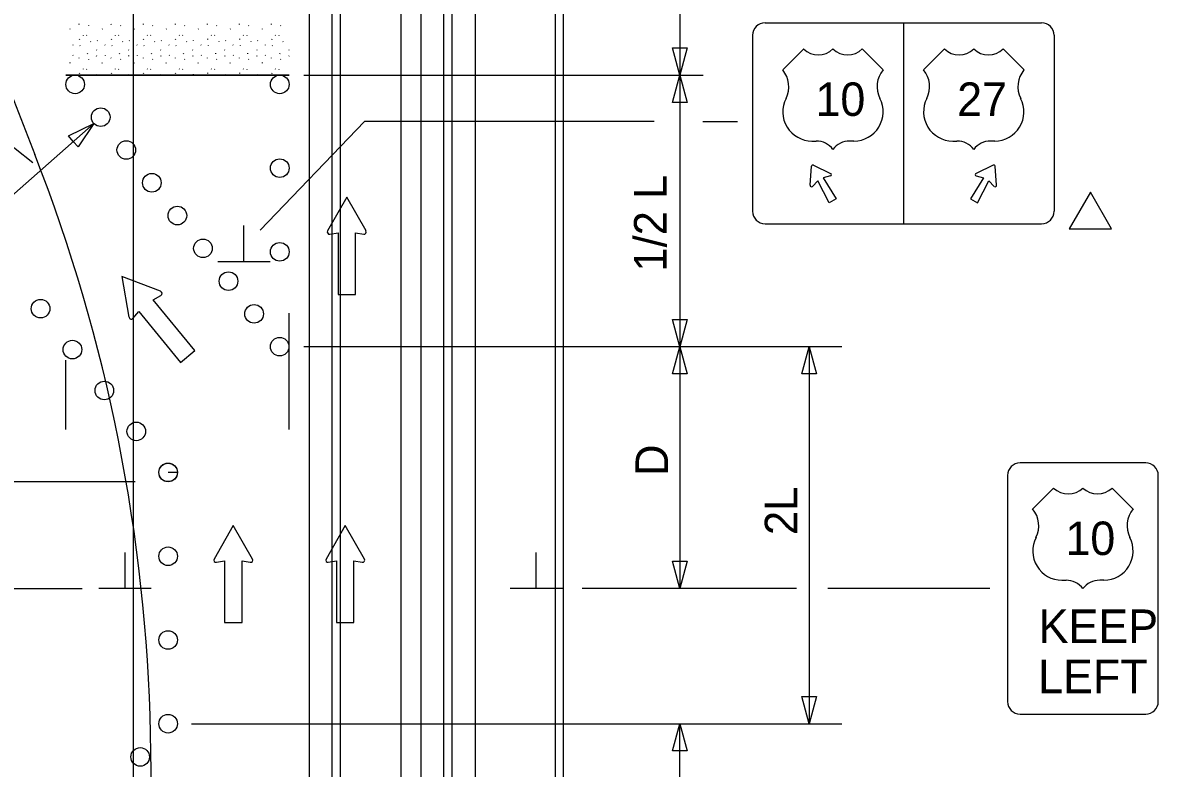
# Model space of a CAD drawing. Extents: x 16715 to 19504, y 7040 to 8495.
# Drawn here: x 16934 to 17178.1, y 7602.5 to 7762.8 of the extents above; entities that cross this region are included whole.
import ezdxf

# ---------------------------------------------------------------- set-up
doc = ezdxf.new("R2010")
doc.units = 0
for name, color, linetype in [('ALI_LEGAL_EX', 7, 'Continuous'), ('MT_SCRATCH_LEVEL_A', 7, 'Continuous'), ('MT_SCRATCH_LEVEL_E', 7, 'Continuous'), ('PAVT_EDGE_EX', 7, 'Continuous'), ('TRAFFIC_SIGNS_PR', 7, 'Continuous'), ('TYPICAL_EX', 7, 'Continuous'), ('TYPICAL_TEXT_DIMEN_PR', 7, 'Continuous')]:
    doc.layers.add(name, color=color, linetype=linetype)

msp = doc.modelspace()

# ---------------------------------------------------------------- linework, layer by layer
at = {"layer": 'ALI_LEGAL_EX'}
for p, q in [((16714.57, 8302.79), (16936.6, 7734.43)), ((16995.53, 8241.3), (16995.53, 7423.16)), ((17019.53, 8241.3), (17019.53, 7423.16)), ((17000.51, 7366.28), (17000.51, 7976.48)), ((17024.51, 7366.28), (17024.51, 7976.48)), ((17048.51, 7366.28), (17048.51, 7976.48)), ((17002.26, 7363.06), (17002.26, 7973.25)), ((17026.26, 7363.06), (17026.26, 7973.25)), ((17050.26, 7363.06), (17050.26, 7973.25)), ((16957.79, 7333.59), (16957.79, 7943.78))]:
    msp.add_line(p, q, dxfattribs=at)
for points in [[(16991.24, 7675.32), (16991.24, 7700.32)], [(16943.24, 7675.32), (16943.24, 7690.24)]]:
    msp.add_lwpolyline(points, dxfattribs=at)
msp.add_arc((16597.56, 7601.98), 364, 341.1474, 21.3382, dxfattribs=at)
at = {"layer": 'MT_SCRATCH_LEVEL_A'}
for p, q in [((16946.07, 7762.54), (16946.08, 7762.43)), ((16948.1, 7762.2), (16948.15, 7762.12)), ((16952.96, 7762.54), (16952.97, 7762.43)), ((16954.99, 7762.2), (16955.04, 7762.12)), ((16959.85, 7762.54), (16959.86, 7762.43)), ((16961.88, 7762.2), (16961.93, 7762.12)), ((16966.73, 7762.54), (16966.75, 7762.43)), ((16968.76, 7762.2), (16968.81, 7762.12)), ((16973.62, 7762.54), (16973.63, 7762.43)), ((16975.65, 7762.2), (16975.7, 7762.12)), ((16980.51, 7762.54), (16980.52, 7762.43)), ((16982.54, 7762.2), (16982.59, 7762.12)), ((16987.4, 7762.54), (16987.41, 7762.43)), ((16989.43, 7762.2), (16989.48, 7762.12)), ((16944.17, 7761.36), (16944.22, 7761.48)), ((16946.96, 7760.13), (16947.01, 7760.05)), ((16947.69, 7760.1), (16947.74, 7760.02)), ((16951.06, 7761.36), (16951.11, 7761.48)), ((16953.84, 7760.13), (16953.89, 7760.05)), ((16954.58, 7760.1), (16954.63, 7760.02)), ((16957.95, 7761.36), (16958, 7761.48)), ((16960.73, 7760.13), (16960.78, 7760.05)), ((16961.47, 7760.1), (16961.52, 7760.02)), ((16964.83, 7761.36), (16964.89, 7761.48)), ((16967.62, 7760.13), (16967.67, 7760.05)), ((16968.35, 7760.1), (16968.41, 7760.02)), ((16971.72, 7761.36), (16971.77, 7761.48)), ((16974.51, 7760.13), (16974.56, 7760.05)), ((16975.24, 7760.1), (16975.29, 7760.02)), ((16978.61, 7761.36), (16978.66, 7761.48)), ((16981.39, 7760.13), (16981.44, 7760.05)), ((16982.13, 7760.1), (16982.18, 7760.02)), ((16985.5, 7761.36), (16985.55, 7761.48)), ((16988.28, 7760.13), (16988.33, 7760.05)), ((16989.02, 7760.1), (16989.07, 7760.02)), ((16944.74, 7758.04), (16944.79, 7757.96)), ((16946.19, 7759.17), (16946.24, 7759.28)), ((16946.27, 7757.9), (16946.32, 7757.82)), ((16948.56, 7758.72), (16948.61, 7758.64)), ((16950.01, 7758.87), (16950.06, 7758.99)), ((16951.63, 7758.04), (16951.68, 7757.96)), ((16953.08, 7759.17), (16953.13, 7759.28)), ((16953.16, 7757.9), (16953.21, 7757.82)), ((16955.45, 7758.72), (16955.5, 7758.64)), ((16956.9, 7758.87), (16956.95, 7758.99)), ((16958.52, 7758.04), (16958.57, 7757.96)), ((16959.97, 7759.17), (16960.02, 7759.28)), ((16960.05, 7757.9), (16960.1, 7757.82)), ((16962.34, 7758.72), (16962.39, 7758.64)), ((16963.78, 7758.87), (16963.84, 7758.99)), ((16965.4, 7758.04), (16965.46, 7757.96)), ((16966.85, 7759.17), (16966.9, 7759.28)), ((16966.93, 7757.9), (16966.99, 7757.82)), ((16969.22, 7758.72), (16969.28, 7758.64)), ((16970.67, 7758.87), (16970.72, 7758.99)), ((16972.29, 7758.04), (16972.34, 7757.96)), ((16973.74, 7759.17), (16973.79, 7759.28)), ((16973.82, 7757.9), (16973.87, 7757.82)), ((16976.11, 7758.72), (16976.16, 7758.64)), ((16977.56, 7758.87), (16977.61, 7758.99)), ((16979.18, 7758.04), (16979.23, 7757.96)), ((16980.63, 7759.17), (16980.68, 7759.28)), ((16980.71, 7757.9), (16980.76, 7757.82)), ((16983, 7758.72), (16983.05, 7758.64)), ((16984.45, 7758.87), (16984.5, 7758.99)), ((16986.07, 7758.04), (16986.12, 7757.96)), ((16987.52, 7759.17), (16987.57, 7759.28)), ((16987.6, 7757.9), (16987.65, 7757.82)), ((16989.89, 7758.72), (16989.94, 7758.64)), ((16944.79, 7755.83), (16944.84, 7755.76)), ((16946.07, 7755.26), (16946.08, 7755.14)), ((16947.91, 7756.11), (16947.96, 7756.23)), ((16948.1, 7754.91), (16948.15, 7754.84)), ((16949.84, 7756.98), (16949.89, 7756.9)), ((16949.88, 7755.58), (16949.93, 7755.7)), ((16951.68, 7755.83), (16951.73, 7755.76)), ((16952.96, 7755.26), (16952.97, 7755.14)), ((16954.8, 7756.11), (16954.85, 7756.23)), ((16954.99, 7754.91), (16955.04, 7754.84)), ((16956.73, 7756.98), (16956.78, 7756.9)), ((16956.77, 7755.58), (16956.82, 7755.7)), ((16958.56, 7755.83), (16958.62, 7755.76)), ((16959.85, 7755.26), (16959.86, 7755.14)), ((16961.69, 7756.11), (16961.74, 7756.23)), ((16961.88, 7754.91), (16961.93, 7754.84)), ((16963.61, 7756.98), (16963.67, 7756.9)), ((16963.66, 7755.58), (16963.71, 7755.7)), ((16965.45, 7755.83), (16965.5, 7755.76)), ((16966.73, 7755.26), (16966.75, 7755.14)), ((16968.58, 7756.11), (16968.63, 7756.23)), ((16968.76, 7754.91), (16968.81, 7754.84)), ((16970.5, 7756.98), (16970.55, 7756.9)), ((16970.54, 7755.58), (16970.6, 7755.7)), ((16972.34, 7755.83), (16972.39, 7755.76)), ((16973.62, 7755.26), (16973.63, 7755.14)), ((16975.46, 7756.11), (16975.51, 7756.23)), ((16975.65, 7754.91), (16975.7, 7754.84)), ((16977.39, 7756.98), (16977.44, 7756.9)), ((16977.43, 7755.58), (16977.48, 7755.7)), ((16979.23, 7755.83), (16979.28, 7755.76)), ((16980.51, 7755.26), (16980.52, 7755.14)), ((16982.35, 7756.11), (16982.4, 7756.23)), ((16982.54, 7754.91), (16982.59, 7754.84)), ((16984.28, 7756.98), (16984.33, 7756.9)), ((16984.32, 7755.58), (16984.37, 7755.7)), ((16986.12, 7755.83), (16986.17, 7755.76)), ((16987.4, 7755.26), (16987.41, 7755.14)), ((16989.24, 7756.11), (16989.29, 7756.23)), ((16989.43, 7754.91), (16989.48, 7754.84)), ((16991.16, 7756.98), (16991.22, 7756.9)), ((16991.21, 7755.58), (16991.24, 7755.67)), ((16944.17, 7754.08), (16944.22, 7754.2)), ((16946.96, 7752.84), (16947.01, 7752.77)), ((16947.69, 7752.81), (16947.74, 7752.74)), ((16951.06, 7754.08), (16951.11, 7754.2)), ((16953.84, 7752.84), (16953.89, 7752.77)), ((16954.58, 7752.81), (16954.63, 7752.74)), ((16957.95, 7754.08), (16958, 7754.2)), ((16960.73, 7752.84), (16960.78, 7752.77)), ((16961.47, 7752.81), (16961.52, 7752.74)), ((16964.83, 7754.08), (16964.89, 7754.2)), ((16967.62, 7752.84), (16967.67, 7752.77)), ((16968.35, 7752.81), (16968.41, 7752.74)), ((16971.72, 7754.08), (16971.77, 7754.2)), ((16974.51, 7752.84), (16974.56, 7752.77)), ((16975.24, 7752.81), (16975.29, 7752.74)), ((16978.61, 7754.08), (16978.66, 7754.2)), ((16981.39, 7752.84), (16981.44, 7752.77)), ((16982.13, 7752.81), (16982.18, 7752.74)), ((16985.5, 7754.08), (16985.55, 7754.2)), ((16988.28, 7752.84), (16988.33, 7752.77)), ((16989.02, 7752.81), (16989.07, 7752.74)), ((16991.24, 7751.52), (16943.24, 7751.52)), ((16943.24, 7751.52), (16991.24, 7751.52)), ((16946.19, 7751.88), (16946.24, 7752)), ((16950.01, 7751.59), (16950.06, 7751.7)), ((16953.08, 7751.88), (16953.13, 7752)), ((16956.9, 7751.59), (16956.95, 7751.7)), ((16959.97, 7751.88), (16960.02, 7752)), ((16963.78, 7751.59), (16963.84, 7751.7)), ((16966.85, 7751.88), (16966.9, 7752)), ((16970.67, 7751.59), (16970.72, 7751.7)), ((16973.74, 7751.88), (16973.79, 7752)), ((16977.56, 7751.59), (16977.61, 7751.7)), ((16980.63, 7751.88), (16980.68, 7752)), ((16984.45, 7751.59), (16984.5, 7751.7)), ((16987.52, 7751.88), (16987.57, 7752))]:
    msp.add_line(p, q, dxfattribs=at)
at = {"layer": 'MT_SCRATCH_LEVEL_E'}
for p, q in [((17003.63, 7725.24), (16999.52, 7718)), ((17007.78, 7718), (17003.63, 7725.24)), ((17000, 7717.32), (17001.78, 7717.63)), ((17001.78, 7717.63), (17001.78, 7704.38)), ((17005.52, 7704.38), (17005.52, 7717.63)), ((17005.52, 7717.63), (17007.3, 7717.32)), ((17001.78, 7704.38), (17005.52, 7704.38)), ((16979.24, 7654.7), (16975.13, 7647.46)), ((16983.39, 7647.46), (16979.24, 7654.7)), ((17003.3, 7654.7), (16999.19, 7647.46)), ((17007.44, 7647.46), (17003.3, 7654.7)), ((16975.62, 7646.78), (16977.39, 7647.1)), ((16977.39, 7647.1), (16977.39, 7633.84)), ((16981.13, 7633.84), (16981.13, 7647.1)), ((16981.13, 7647.1), (16982.91, 7646.78)), ((16999.67, 7646.78), (17001.44, 7647.1)), ((17001.44, 7647.1), (17001.44, 7633.84)), ((17005.19, 7633.84), (17005.19, 7647.1)), ((17005.19, 7647.1), (17006.96, 7646.78)), ((16977.39, 7633.84), (16981.13, 7633.84)), ((17001.44, 7633.84), (17005.19, 7633.84))]:
    msp.add_line(p, q, dxfattribs=at)
for centre, start, end in [((16999.92, 7717.78), 150.4248, 279.9638), ((17007.36, 7717.78), 260.0362, 29.7731), ((16975.54, 7647.24), 150.4248, 279.9638), ((16982.98, 7647.24), 260.0362, 29.7731), ((16999.59, 7647.24), 150.4248, 279.9638), ((17007.03, 7647.24), 260.0362, 29.7731)]:
    msp.add_arc(centre, 0.463, start, end, dxfattribs=at)
at = {"layer": 'PAVT_EDGE_EX'}
for p, q in [((17015.24, 7785.52), (17015.24, 7430.94)), ((17031.24, 7785.52), (17031.24, 7430.94))]:
    msp.add_line(p, q, dxfattribs=at)
at = {"layer": 'TRAFFIC_SIGNS_PR'}
for p, q in [((17093.58, 7762.77), (17152.98, 7762.77)), ((17123.28, 7762.77), (17123.28, 7719.57)), ((17090.88, 7760.07), (17090.88, 7722.27)), ((17155.68, 7760.07), (17155.68, 7722.27)), ((17103.23, 7727.84), (17103.55, 7731.91)), ((17103.97, 7732.15), (17107.65, 7730.39)), ((17142.59, 7732.15), (17138.9, 7730.39)), ((17143.33, 7727.84), (17143.01, 7731.91)), ((17093.58, 7719.57), (17152.98, 7719.57)), ((17175.37, 7668.13), (17148.37, 7668.13)), ((17145.67, 7665.43), (17145.67, 7616.83)), ((17178.07, 7616.83), (17178.07, 7665.43)), ((17148.37, 7614.13), (17175.37, 7614.13))]:
    msp.add_line(p, q, dxfattribs=at)
for points in [[(17107.61, 7729.84), (17106.03, 7729.41), (17108.85, 7724.93), (17107.36, 7724.07), (17104.9, 7728.76), (17103.73, 7727.6)], [(17138.95, 7729.84), (17140.53, 7729.41), (17137.7, 7724.93), (17139.2, 7724.07), (17141.66, 7728.76), (17142.83, 7727.6)]]:
    msp.add_lwpolyline(points, dxfattribs=at)
for centre in [(16945.25, 7749.52), (16945.25, 7749.52), (16989.24, 7749.52), (16950.75, 7742.47), (16956.24, 7735.42), (16989.24, 7731.52), (16961.74, 7728.37), (16967.23, 7721.32), (16972.73, 7714.27), (16989.24, 7713.52), (16978.22, 7707.22), (16937.82, 7701.3), (16983.72, 7700.18), (16944.67, 7692.5), (16989.21, 7693.13), (16951.53, 7683.71), (16958.39, 7674.91), (16965.24, 7666.12), (16965.24, 7666.07), (16965.24, 7648.07), (16965.24, 7630.07), (16965.24, 7612.07), (16959.24, 7604.93)]:
    msp.add_circle(centre, 2, dxfattribs=at)
for centre, radius, start, end in [((17093.58, 7760.07), 2.7, 90, 180), ((17093.58, 7760.07), 2.7, 90, 180), ((17152.98, 7760.07), 2.7, 0, 90), ((17103.84, 7731.89), 0.293, 64.4823, 175.5177), ((17107.53, 7730.13), 0.293, 285.9885, 64.4823), ((17139.03, 7730.13), 0.293, 115.5177, 254.0115), ((17142.72, 7731.89), 0.293, 4.4823, 115.5177), ((17103.52, 7727.81), 0.293, 175.5177, 314.0115), ((17143.04, 7727.81), 0.293, 225.9885, 4.4823), ((17093.58, 7722.27), 2.7, 180, 270), ((17152.98, 7722.27), 2.7, 270, 0), ((17148.37, 7665.43), 2.7, 90, 180), ((17175.37, 7665.43), 2.7, 0, 90), ((17148.37, 7616.83), 2.7, 180, 270), ((17175.37, 7616.83), 2.7, 270, 0)]:
    msp.add_arc(centre, radius, start, end, dxfattribs=at)
at = {"layer": 'TYPICAL_EX'}
for p, q in [((17097.35, 7752.64), (17101.85, 7757.14)), ((17118.95, 7752.64), (17114.45, 7757.14)), ((17127.61, 7752.64), (17132.11, 7757.14)), ((17149.21, 7752.64), (17144.71, 7757.14)), ((17103.64, 7737.33), (17104.54, 7737.33)), ((17112.65, 7737.33), (17111.75, 7737.33)), ((17133.9, 7737.33), (17134.8, 7737.33)), ((17142.92, 7737.33), (17142.02, 7737.33)), ((17151.07, 7658.23), (17155.57, 7662.73)), ((17172.68, 7658.23), (17168.17, 7662.73)), ((17157.37, 7642.92), (17158.27, 7642.92)), ((17166.38, 7642.92), (17165.48, 7642.92))]:
    msp.add_line(p, q, dxfattribs=at)
for centre, radius, start, end in [((17105, 7760.42), 4.55, 226.1404, 313.8596), ((17111.3, 7760.42), 4.55, 226.1404, 313.8596), ((17135.26, 7760.42), 4.55, 226.1404, 313.8596), ((17141.56, 7760.42), 4.55, 226.1404, 313.8596), ((17093.08, 7749.04), 5.58, 333.0977, 40.1936), ((17123.21, 7749.04), 5.58, 139.8064, 206.9023), ((17123.34, 7749.04), 5.58, 333.0977, 40.1936), ((17153.47, 7749.04), 5.58, 139.8064, 206.9023), ((17103.65, 7743.62), 6.29, 152.6698, 269.9013), ((17112.64, 7743.62), 6.29, 270.0987, 27.3302), ((17133.91, 7743.62), 6.29, 152.6698, 269.9013), ((17142.9, 7743.62), 6.29, 270.0987, 27.3302), ((17104.55, 7732.82), 4.51, 37.1038, 90.1385), ((17111.74, 7732.82), 4.51, 89.8615, 142.8962), ((17134.81, 7732.82), 4.51, 37.1038, 90.1385), ((17142, 7732.82), 4.51, 89.8615, 142.8962), ((17158.73, 7666.01), 4.55, 226.1404, 313.8596), ((17165.02, 7666.01), 4.55, 226.1404, 313.8596), ((17146.81, 7654.63), 5.58, 333.0977, 40.1936), ((17176.94, 7654.63), 5.58, 139.8064, 206.9023), ((17157.38, 7649.21), 6.29, 152.6698, 269.9013), ((17166.37, 7649.21), 6.29, 270.0987, 27.3302), ((17158.28, 7638.41), 4.51, 37.1038, 90.1385), ((17165.47, 7638.41), 4.51, 89.8615, 142.8962)]:
    msp.add_arc(centre, radius, start, end, dxfattribs=at)
at = {"layer": 'TYPICAL_TEXT_DIMEN_PR'}
for p, q in [((17075.24, 7774.07), (17075.24, 7751.52)), ((17075.24, 7751.52), (17073.67, 7757.38)), ((17073.67, 7757.38), (17075.24, 7757.38)), ((17075.24, 7757.38), (17076.81, 7757.38)), ((17076.81, 7757.38), (17075.24, 7751.52)), ((16994.44, 7751.52), (17080.24, 7751.52)), ((17073.67, 7745.66), (17075.24, 7751.52)), ((17075.24, 7751.52), (17075.24, 7693.13)), ((17075.24, 7751.52), (17076.81, 7745.66)), ((17075.24, 7745.66), (17073.67, 7745.66)), ((17076.81, 7745.66), (17075.24, 7745.66)), ((16925.6, 7720.21), (16949.25, 7741.14)), ((16936.15, 7732.63), (16926.29, 7740.44)), ((16943.82, 7738.43), (16949.25, 7741.14)), ((16949.25, 7741.14), (16945.9, 7736.08)), ((16985.06, 7718.16), (17007.43, 7741.51)), ((17069.73, 7741.51), (17007.43, 7741.51)), ((17080.21, 7741.51), (17087.66, 7741.51)), ((16944.86, 7737.26), (16943.82, 7738.43)), ((16945.9, 7736.08), (16944.86, 7737.26)), ((16981.52, 7711.4), (16981.52, 7719.18)), ((16987.15, 7711.4), (16975.9, 7711.4)), ((16963.63, 7705.03), (16955.31, 7708.19)), ((16955.31, 7708.19), (16956.83, 7699.44)), ((16962.03, 7703.2), (16963.7, 7704.14)), ((16971.01, 7692.28), (16962.03, 7703.2)), ((16957.69, 7699.2), (16958.94, 7700.66)), ((16958.94, 7700.66), (16967.93, 7689.74)), ((17075.24, 7693.13), (17073.67, 7698.99)), ((17073.67, 7698.99), (17075.24, 7698.99)), ((17075.24, 7698.99), (17076.81, 7698.99)), ((17076.81, 7698.99), (17075.24, 7693.13)), ((16967.93, 7689.74), (16971.01, 7692.28)), ((17110.03, 7693.13), (16994.44, 7693.13)), ((17073.67, 7687.27), (17075.24, 7693.13)), ((17075.24, 7693.13), (17076.81, 7687.27)), ((17075.24, 7693.13), (17075.24, 7641.12)), ((17101.48, 7687.27), (17103.05, 7693.13)), ((17103.05, 7693.13), (17103.05, 7612.07)), ((17103.05, 7693.13), (17104.62, 7687.27)), ((17075.24, 7687.27), (17073.67, 7687.27)), ((17076.81, 7687.27), (17075.24, 7687.27)), ((17103.05, 7687.27), (17101.48, 7687.27)), ((17104.62, 7687.27), (17103.05, 7687.27)), ((16965.24, 7666.12), (16967.24, 7666.12)), ((16958.13, 7664.07), (16854.24, 7664.07)), ((16955.99, 7641.12), (16955.99, 7648.91)), ((17044.37, 7641.12), (17044.37, 7648.91)), ((17075.24, 7641.12), (17073.67, 7646.99)), ((17073.67, 7646.99), (17075.24, 7646.99)), ((17075.24, 7646.99), (17076.81, 7646.99)), ((17076.81, 7646.99), (17075.24, 7641.12)), ((16825.81, 7641.12), (16946.75, 7641.12)), ((16961.62, 7641.12), (16950.37, 7641.12)), ((17049.99, 7641.12), (17038.74, 7641.12)), ((17100.32, 7641.12), (17054.24, 7641.12)), ((17141.86, 7641.12), (17107.05, 7641.12)), ((17103.05, 7612.07), (17101.48, 7617.93)), ((17101.48, 7617.93), (17103.05, 7617.93)), ((17103.05, 7617.93), (17104.62, 7617.93)), ((17104.62, 7617.93), (17103.05, 7612.07)), ((16970.29, 7612.07), (17110.03, 7612.07)), ((17073.67, 7606.21), (17075.24, 7612.07)), ((17075.24, 7583.51), (17075.24, 7612.07)), ((17075.24, 7612.07), (17076.81, 7606.21)), ((17075.24, 7606.21), (17073.67, 7606.21)), ((17076.81, 7606.21), (17075.24, 7606.21))]:
    msp.add_line(p, q, dxfattribs=at)
msp.add_lwpolyline([(17163.48, 7726.33), (17158.95, 7718.49), (17168.01, 7718.49)], close=True, dxfattribs=at)
for centre, start, end in [((16963.45, 7704.57), 299.4884, 69.2254), ((16957.32, 7699.53), 189.8771, 319.4161)]:
    msp.add_arc(centre, 0.494, start, end, dxfattribs=at)

# ---------------------------------------------------------------- texts
at = {"layer": 'TRAFFIC_SIGNS_PR'}
for s, p in [('10', (17104.39, 7742.74)), ('27', (17134.84, 7742.74)), ('10', (17158.12, 7648.33)), ('KEEP', (17152.35, 7629.43)), ('LEFT', (17152.25, 7618.63))]:
    msp.add_text(s, height=7.2, dxfattribs=at).set_placement(p)
at = {"layer": 'TYPICAL_TEXT_DIMEN_PR'}
for s, p in [('1/2 L', (17072.38, 7709.26)), ('D', (17072.69, 7665.34)), ('2L', (17100.49, 7652.63))]:
    msp.add_text(s, height=7, rotation=90, dxfattribs=at).set_placement(p)

doc.saveas('drawing.dxf')
